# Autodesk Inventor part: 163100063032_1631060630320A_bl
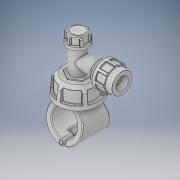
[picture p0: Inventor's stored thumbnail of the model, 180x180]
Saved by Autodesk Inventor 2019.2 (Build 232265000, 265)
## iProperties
Created: 2022-02
Part Number: 163100063032_1631060630320A_bl
Material: Generic
Description: Plassadle Tapper 63x25
Document SubType Name: Modeling
Designer: comp2
Density: 1 g/cm^3
Appearance: Default
Author: comp2
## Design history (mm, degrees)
derived "16310.ipt"
feature "Solid1::16310.ipt" dims "ScaleForDerivedMember" = 10
feature "Solid2::16310.ipt" dims "ScaleForDerivedMember" = 10
feature "Solid3::16310.ipt" dims "ScaleForDerivedMember" = 10
feature "Solid4::16310.ipt" dims "ScaleForDerivedMember" = 10
tag "TaggingFeature1"
body "Solid1"
body "Solid2"
body "Solid3"
body "Solid4"
other parameters: "d" = 63 [user parameter], "d1" = 32 [user parameter], "B" = 91 [user parameter], "L" = 89 [user parameter], "E_" = 64 [user parameter], "E1" = 102 [user parameter], "H1" = 231 [user parameter], "H2" = 144 [user parameter], "H3" = 111 [user parameter], "H_costum" = 49 [user parameter], "d0" = 63 [user parameter], "d2" = 91 [user parameter], "d3" = 31.5 [user parameter], "d5" = 231 [user parameter], "d7" = 86.45 [user parameter], "d8" = 85 deg [user parameter], "d9" = 45 deg [user parameter], "d10" = 102 [user parameter], "d11" = 49 [user parameter], "d12" = 34.3 [user parameter], "d13" = 35.7 [user parameter], "d14" = 55.08 [user parameter], "d15" = 2.45 [user parameter], "d16" = 2 [user parameter], "d17" = 2 [user parameter], "d18" = 29.4 [user parameter], "d19" = 7.35 [user parameter], "d20" = 1 [user parameter], "d21" = 30.6 [user parameter], "d22" = 1 [user parameter], "d23" = 14.7 [user parameter], "d24" = 111 [user parameter], "d27" = 144 [user parameter], "d29" = 64 [user parameter], "d31" = 51.2 [user parameter], "d32" = 44.4 [user parameter], "d33" = 15.54 [user parameter], "d34" = 93 deg [user parameter], "d35" = 2 [user parameter], "d36" = 4 [user parameter], "d39" = 45 deg [user parameter], "d40" = 4 [user parameter], "d41" = 5 [user parameter], "d42" = 2.8 [user parameter], "d46" = 51 [user parameter], "d47" = 32 [user parameter], "d48" = 49 [user parameter], "d49" = 1.82 [user parameter], "d50" = 89 [user parameter], "d51" = 0 [user parameter], "d52" = 19.6 [user parameter], "d53" = 50.05 [user parameter], "d54" = 31.15 [user parameter], "d55" = 0 [user parameter], "d56" = 17.8 [user parameter], "d57" = 17.8 [user parameter], "d59" = 0 [user parameter], "d60" = 89 [user parameter], "d61" = 0 [user parameter], "d62" = 31.15 [user parameter], "d63" = 0 [user parameter], "d65" = 0 [user parameter], "d67" = 0 [user parameter], "d69" = 0 [user parameter], "d70" = 1 [user parameter], "d71" = 85.44 [user parameter], "d72" = 0 [user parameter], "d73" = 2 [user parameter], "d77" = 32 [user parameter], "d78" = 86.7 [user parameter], "d79" = 5.1 [user parameter], "d80" = 60 deg [user parameter], "d81" = 5.1 [user parameter], "d84" = 0 [user parameter], "d85" = 1 [user parameter], "d87" = 360 deg [user parameter], "d90" = 0 [user parameter], "d91" = 1 [user parameter], "d93" = 60 deg [user parameter], "d94" = 3.06 [user parameter], "d95" = 3.06 [user parameter], "d97" = 0 [user parameter], "d98" = 0.5 [user parameter], "d100" = 360 deg [user parameter], "d102" = 2 [user parameter], "d105" = 0 [user parameter], "d106" = 45 deg [user parameter], "d107" = 3.2 [user parameter], "d108" = 3.2 [user parameter], "d109" = 2.95332 [user parameter], "d110" = -8 [user parameter], "d112" = 0 [user parameter], "d113" = 0.5 [user parameter], "d115" = 360 deg [user parameter], "d117" = 0.5 [user parameter]
